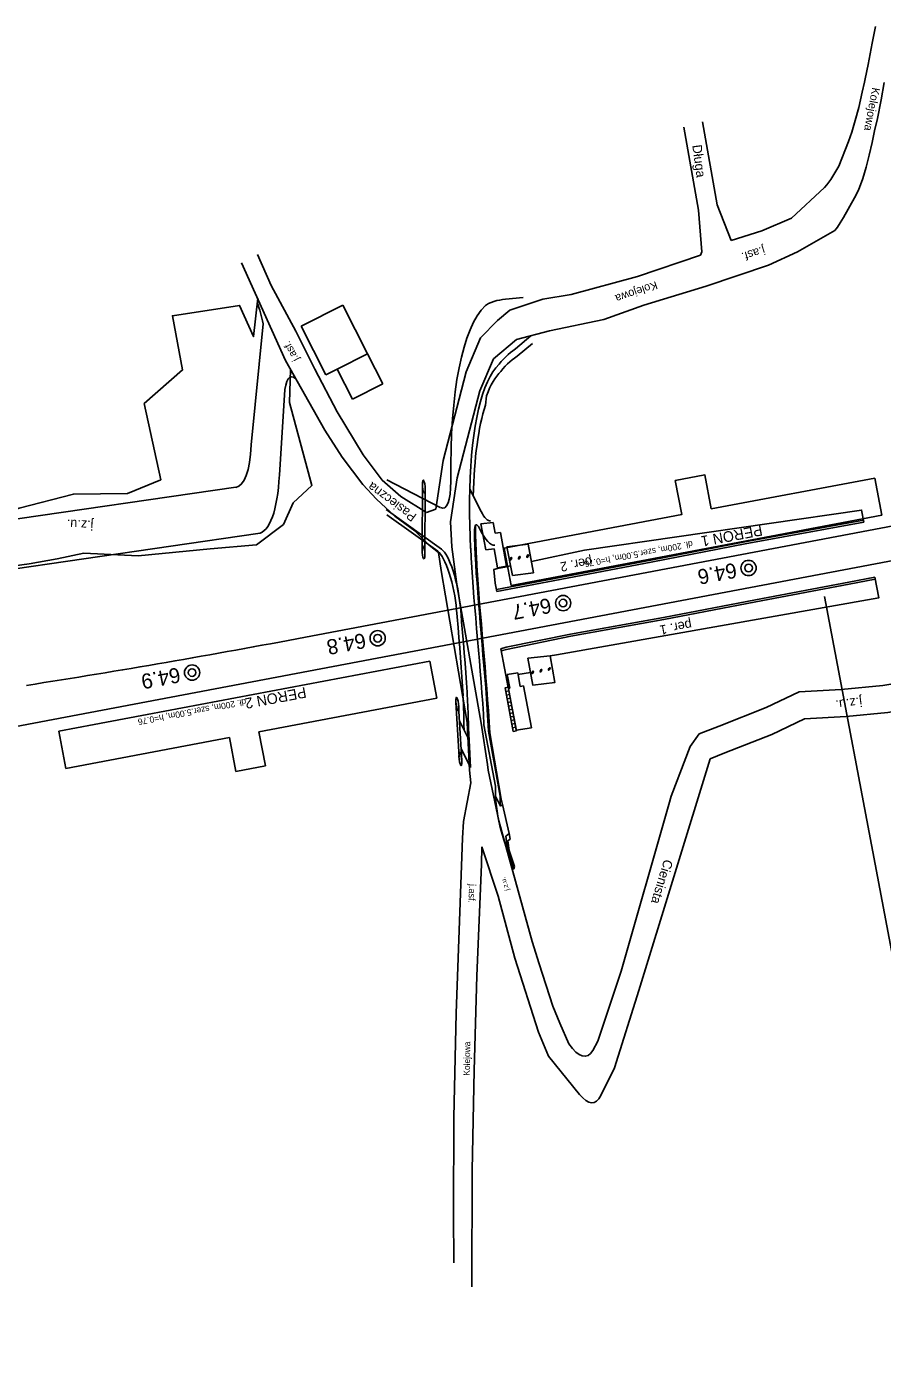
# Model space of a CAD drawing. Extents: x 6541740 to 6556805, y 5525233 to 5530361.
# Drawn here: x 6556344.1 to 6556457.6, y 5525917.2 to 5526092.1 of the extents above; entities that cross this region are included whole.
import ezdxf

# ---------------------------------------------------------------- set-up
doc = ezdxf.new("R2010")
doc.units = 0
for name, color, linetype in [('Default', 7, 'Continuous'), ('TOR_SCH-budynki', 7, 'Continuous'), ('TOR_SCH-hektometry', 7, 'Continuous'), ('TOR_SCH-obiekty istniejace', 7, 'Continuous'), ('TOR_SCH-obiekty projektowane', 7, 'Continuous'), ('TOR_SCH-opisy glowne', 7, 'Continuous'), ('TOR_SCH-perony', 7, 'Continuous'), ('TOR_SCH-przejazdy+drogi istniejace', 7, 'Continuous'), ('TOR_SCH-przejazdy+drogi projektowane', 7, 'Continuous'), ('TOR_SCH-tory projektowane', 7, 'Continuous')]:
    doc.layers.add(name, color=color, linetype=linetype)

# ---------------------------------------------------------------- blocks, each defined once
blk = doc.blocks.new('4010_1')
at = {"layer": 'Default'}
for radius in [0.75, 0.375]:
    blk.add_circle((0, 0), radius, dxfattribs=at)
blk = doc.blocks.new('311_2')
at = {"layer": 'Default'}
blk.add_circle((0, 0), 0.25, dxfattribs=at)

msp = doc.modelspace()

# ---------------------------------------------------------------- linework, layer by layer
at = {"layer": 'TOR_SCH-budynki'}
for p, q in [((6556380.55, 5526052.44), (6556386.06, 5526055.23)), ((6556386.06, 5526055.23), (6556389.33, 5526048.76)), ((6556383.82, 5526045.97), (6556380.55, 5526052.44)), ((6556389.33, 5526048.76), (6556385.3, 5526046.71)), ((6556389.33, 5526048.76), (6556391.35, 5526044.8)), ((6556385.3, 5526046.71), (6556383.82, 5526045.97)), ((6556387.33, 5526042.77), (6556385.3, 5526046.71)), ((6556391.35, 5526044.8), (6556387.33, 5526042.77)), ((6556404.35, 5526026.23), (6556405.97, 5526026.43)), ((6556404.98, 5526022.81), (6556404.35, 5526026.23)), ((6556406.23, 5526025), (6556405.97, 5526026.43)), ((6556406.23, 5526025), (6556406.92, 5526025.09)), ((6556407.74, 5526020.65), (6556406.92, 5526025.09)), ((6556404.98, 5526022.81), (6556406.09, 5526022.94)), ((6556406.56, 5526020.41), (6556406.09, 5526022.94)), ((6556406.56, 5526020.41), (6556407.74, 5526020.65)), ((6556407.83, 5526006.29), (6556409.22, 5526006.51)), ((6556408.17, 5526004.46), (6556407.83, 5526006.29)), ((6556409.56, 5526004.68), (6556409.22, 5526006.51)), ((6556407.95, 5526004.58), (6556407.54, 5526004.5)), ((6556407.98, 5526004.43), (6556408.17, 5526004.46)), ((6556409.03, 5525998.89), (6556407.98, 5526004.43)), ((6556409.56, 5526004.68), (6556410.01, 5526004.76)), ((6556411.04, 5525999.23), (6556410.01, 5526004.76)), ((6556409.03, 5525998.89), (6556411.04, 5525999.23))]:
    msp.add_line(p, q, dxfattribs=at)
msp.add_lwpolyline([(6556409.04, 5525998.82), (6556408.64, 5525998.74), (6556407.54, 5526004.5), (6556407.95, 5526004.58)], close=True, dxfattribs=at)
at = {"layer": 'TOR_SCH-obiekty istniejace'}
for p, q in [((6556455.03, 5526026.74), (6556439.3, 5526023.84)), ((6556455.08, 5526026.47), (6556439.35, 5526023.58)), ((6556407.68, 5526009.88), (6556406.97, 5526009.69)), ((6556406.97, 5526009.7), (6556407.95, 5526004.57)), ((6556407.73, 5526009.61), (6556407.02, 5526009.42)), ((6556407.64, 5526004.02), (6556408.04, 5526004.1)), ((6556407.73, 5526003.54), (6556408.13, 5526003.61)), ((6556407.82, 5526003.06), (6556408.22, 5526003.13)), ((6556407.91, 5526002.58), (6556408.31, 5526002.65)), ((6556408, 5526002.1), (6556408.41, 5526002.17)), ((6556408.09, 5526001.61), (6556408.5, 5526001.69)), ((6556408.18, 5526001.13), (6556408.59, 5526001.21)), ((6556408.27, 5526000.65), (6556408.68, 5526000.73)), ((6556408.36, 5526000.17), (6556408.77, 5526000.25)), ((6556408.46, 5525999.69), (6556408.86, 5525999.77)), ((6556408.55, 5525999.21), (6556408.95, 5525999.29)), ((6556409.04, 5525998.82), (6556408.64, 5525998.74))]:
    msp.add_line(p, q, dxfattribs=at)
for points in [[(6556455.08, 5526026.47), (6556454.77, 5526028.06), (6556418.06, 5526022.75), (6556411.03, 5526021.25)], [(6556439.3, 5526023.84), (6556427.06, 5526021.46), (6556414.8, 5526019.14), (6556406.41, 5526017.56)], [(6556439.35, 5526023.57), (6556427.12, 5526021.19), (6556414.85, 5526018.87), (6556406.46, 5526017.29)], [(6556408.28, 5526020.66), (6556407.73, 5526020.54), (6556406.55, 5526020.32), (6556406.06, 5526020.21), (6556406.25, 5526018.39), (6556406.46, 5526017.29)], [(6556456.51, 5526019.19), (6556453.07, 5526018.53), (6556440.73, 5526016.19), (6556428.54, 5526013.84), (6556416.23, 5526011.62), (6556407.68, 5526009.88)], [(6556456.56, 5526018.92), (6556453.12, 5526018.26), (6556440.78, 5526015.92), (6556428.59, 5526013.57), (6556416.28, 5526011.35), (6556407.73, 5526009.61)], [(6556456.51, 5526019.19), (6556457.05, 5526016.42), (6556414.35, 5526008.87), (6556413.51, 5526008.75)], [(6556410.92, 5526006.56), (6556409.26, 5526006.27)]]:
    msp.add_lwpolyline(points, dxfattribs=at)
for points in [[(6556408.53, 5526019.4), (6556411.31, 5526019.76), (6556410.6, 5526023.56), (6556407.79, 5526023.19)], [(6556410.57, 5526008.46), (6556413.51, 5526008.75), (6556414.14, 5526005.23), (6556411.23, 5526004.86)]]:
    msp.add_lwpolyline(points, close=True, dxfattribs=at)
at = {"layer": 'TOR_SCH-obiekty projektowane'}
for p, q in [((6556396.55, 5526022.78), (6556396.59, 5526031.52)), ((6556396.92, 5526022.1), (6556396.96, 5526030.84)), ((6556401.45, 5525995.33), (6556401.03, 5526002.62)), ((6556401.82, 5525994.84), (6556401.4, 5526002.12))]:
    msp.add_line(p, q, dxfattribs=at)
for centre, major_axis, ratio in [((6556396.78, 5526031.18), (0.074, -0.847), 0.2003), ((6556396.74, 5526022.44), (0.074, -0.847), 0.2003), ((6556401.22, 5526002.37), (0.101, -0.896), 0.178041), ((6556401.63, 5525995.08), (0.101, -0.896), 0.178041)]:
    msp.add_ellipse(centre, major_axis=major_axis, ratio=ratio, dxfattribs=at)
at = {"layer": 'TOR_SCH-opisy glowne'}
msp.add_lwpolyline([(6556465.13, 5525935.87), (6556449.87, 5526016.63), (6556449.87, 5526016.63), (6556449.87, 5526016.63)], dxfattribs=at)
at = {"layer": 'TOR_SCH-perony'}
for p, q in [((6556456.53, 5526032.31), (6556434.87, 5526028.21)), ((6556456.53, 5526032.31), (6556457.46, 5526027.4)), ((6556457.46, 5526027.4), (6556408.34, 5526018.09)), ((6556407.41, 5526023), (6556408.34, 5526018.09)), ((6556397.58, 5526008.06), (6556348.45, 5525998.75)), ((6556397.58, 5526008.06), (6556398.51, 5526003.15)), ((6556348.45, 5525998.75), (6556349.38, 5525993.84)), ((6556371.04, 5525997.94), (6556349.38, 5525993.84)), ((6556371.9, 5525993.42), (6556371.04, 5525997.94)), ((6556375.81, 5525994.16), (6556371.9, 5525993.42))]:
    msp.add_line(p, q, dxfattribs=at)
for points in [[(6556434.87, 5526028.21), (6556434.01, 5526032.73), (6556430.1, 5526031.99)], [(6556430.1, 5526031.99), (6556430.96, 5526027.47), (6556407.41, 5526023)], [(6556398.51, 5526003.15), (6556374.95, 5525998.68), (6556375.81, 5525994.16)]]:
    msp.add_lwpolyline(points, dxfattribs=at)
at = {"layer": 'TOR_SCH-przejazdy+drogi istniejace'}
for p, q in [((6556456.62, 5526092.14), (6556456.19, 5526089.94)), ((6556456.19, 5526089.94), (6556455.65, 5526087.08)), ((6556455.65, 5526087.08), (6556455.25, 5526085.22)), ((6556455.25, 5526085.22), (6556455.14, 5526084.75)), ((6556454.83, 5526083.41), (6556454.39, 5526081.4)), ((6556455.14, 5526084.75), (6556454.83, 5526083.41)), ((6556457.36, 5526082.42), (6556457.77, 5526084.72)), ((6556454.39, 5526081.4), (6556453.93, 5526079.68)), ((6556456.87, 5526079.96), (6556457.36, 5526082.42)), ((6556453.93, 5526079.68), (6556453.48, 5526078.12)), ((6556456.5, 5526078.29), (6556456.87, 5526079.96)), ((6556433.19, 5526067.78), (6556431.21, 5526078.78)), ((6556433.7, 5526079.51), (6556435.66, 5526068.52)), ((6556453.48, 5526078.12), (6556453.06, 5526076.91)), ((6556456.16, 5526076.78), (6556456.5, 5526078.29)), ((6556453.06, 5526076.91), (6556451.76, 5526073.62)), ((6556455.77, 5526075.1), (6556456.16, 5526076.78)), ((6556455.38, 5526073.5), (6556455.77, 5526075.1)), ((6556451.25, 5526072.73), (6556450.7, 5526071.88)), ((6556451.76, 5526073.62), (6556451.25, 5526072.73)), ((6556454.96, 5526072), (6556455.38, 5526073.5)), ((6556450.15, 5526071.17), (6556449.86, 5526070.82)), ((6556450.7, 5526071.88), (6556450.15, 5526071.17)), ((6556454.37, 5526070.45), (6556454.96, 5526072)), ((6556445.48, 5526066.74), (6556449.86, 5526070.82)), ((6556452.39, 5526066.81), (6556453.85, 5526069.43)), ((6556453.85, 5526069.43), (6556454.37, 5526070.45)), ((6556433.59, 5526062.26), (6556433.19, 5526067.78)), ((6556435.66, 5526068.52), (6556437.49, 5526063.78)), ((6556441.56, 5526065.05), (6556445.48, 5526066.74)), ((6556451.6, 5526065.54), (6556451.94, 5526066.1)), ((6556451.94, 5526066.1), (6556452.39, 5526066.81)), ((6556441.56, 5526065.05), (6556437.49, 5526063.78)), ((6556451.22, 5526065.09), (6556446.28, 5526062.28)), ((6556451.22, 5526065.09), (6556451.6, 5526065.54)), ((6556433.59, 5526062.26), (6556433.42, 5526061.83)), ((6556446.28, 5526062.28), (6556442.45, 5526060.53)), ((6556378.44, 5526047.89), (6556372.63, 5526060.82)), ((6556374.74, 5526061.92), (6556376.58, 5526057.81)), ((6556442.45, 5526060.53), (6556434.17, 5526057.72)), ((6556376.58, 5526057.81), (6556379.83, 5526051.77)), ((6556379.83, 5526051.77), (6556382.34, 5526046.71)), ((6556383.68, 5526038.66), (6556378.44, 5526047.89)), ((6556382.34, 5526046.71), (6556385.29, 5526041.08)), ((6556385.29, 5526041.08), (6556388.76, 5526035.37)), ((6556385.97, 5526035.06), (6556383.68, 5526038.66)), ((6556388.71, 5526031.46), (6556385.97, 5526035.06)), ((6556388.76, 5526035.37), (6556391.27, 5526032.01)), ((6556357.54, 5526030.26), (6556361.94, 5526032.06)), ((6556390.52, 5526029.51), (6556388.71, 5526031.46)), ((6556391.27, 5526032.01), (6556393.73, 5526029.86)), ((6556392.95, 5526027.24), (6556390.52, 5526029.51)), ((6556393.73, 5526029.86), (6556397.14, 5526027.75)), ((6556395.59, 5526025.33), (6556392.95, 5526027.24)), ((6556397.14, 5526027.75), (6556398.36, 5526028.18)), ((6556397.49, 5526023.42), (6556395.59, 5526025.33)), ((6556398.72, 5526022.45), (6556397.49, 5526023.42)), ((6556434.7, 5525995.11), (6556425.26, 5525964.4)), ((6556403.02, 5525991.93), (6556402.85, 5525993.6)), ((6556405.33, 5525993.59), (6556406.72, 5525986.89)), ((6556402.05, 5525986.82), (6556403.02, 5525991.93)), ((6556422.91, 5525966.97), (6556429.23, 5525989.04)), ((6556401.91, 5525984.59), (6556402.05, 5525986.82)), ((6556406.72, 5525986.89), (6556411.15, 5525970.92)), ((6556401.08, 5525961.39), (6556401.91, 5525984.59)), ((6556404.49, 5525983.43), (6556404.42, 5525981.12)), ((6556406.64, 5525976.92), (6556404.49, 5525983.43)), ((6556404.42, 5525981.12), (6556403.82, 5525966.35)), ((6556408.86, 5525968.68), (6556406.64, 5525976.92)), ((6556408.86, 5525968.68), (6556411.99, 5525958.89)), ((6556403.82, 5525966.35), (6556403.44, 5525953.83)), ((6556419.85, 5525957.71), (6556422.91, 5525966.97)), ((6556425.26, 5525964.4), (6556422.03, 5525954.15)), ((6556400.76, 5525947.58), (6556401.08, 5525961.39)), ((6556419.19, 5525956.48), (6556419.85, 5525957.71)), ((6556403.44, 5525953.83), (6556403.21, 5525940.6)), ((6556422.03, 5525954.15), (6556420.24, 5525950.51)), ((6556400.72, 5525934.88), (6556400.76, 5525947.58)), ((6556403.21, 5525940.6), (6556403.16, 5525925.15)), ((6556400.78, 5525928.33), (6556400.72, 5525934.88))]:
    msp.add_line(p, q, dxfattribs=at)
for points in [[(6556406.55, 5526053.17), (6556408.16, 5526054.56), (6556412.53, 5526056.01), (6556416.29, 5526056.63), (6556425.11, 5526058.99), (6556433.42, 5526061.83)], [(6556406.03, 5526048.1), (6556409.06, 5526050.66), (6556413.45, 5526051.8), (6556420.65, 5526053.29), (6556425.91, 5526055.22), (6556434.17, 5526057.72)], [(6556361.94, 5526032.06), (6556359.76, 5526042.18), (6556364.83, 5526046.64), (6556363.49, 5526053.81), (6556372.39, 5526055.17), (6556374.24, 5526051.04), (6556374.79, 5526056.16)], [(6556398.36, 5526028.18), (6556399.33, 5526034.63), (6556402.41, 5526046.4), (6556404.31, 5526050.87), (6556406.55, 5526053.17)], [(6556358.96, 5526022.02), (6556368.49, 5526022.94), (6556374.61, 5526023.44), (6556378.19, 5526026.14), (6556379.47, 5526029), (6556381.95, 5526031.33), (6556378.97, 5526042.31), (6556379.13, 5526046.68), (6556379.13, 5526046.68), (6556379.13, 5526046.68)], [(6556405.33, 5525993.59), (6556405.23, 5525994.36), (6556404.4, 5525999.82), (6556401.21, 5526017.88), (6556400.48, 5526023.18), (6556400.33, 5526026.51), (6556401.21, 5526032.34), (6556404.22, 5526043.86), (6556406.03, 5526048.11)], [(6556301.03, 5526021), (6556308.94, 5526022.23), (6556312.43, 5526023.7), (6556323.46, 5526023.91), (6556326.25, 5526024.08), (6556330.73, 5526025.47), (6556332.55, 5526025.73), (6556335.44, 5526025.81), (6556343.2, 5526028.3), (6556350.37, 5526030.18), (6556357.54, 5526030.26)], [(6556302.27, 5526014.25), (6556310.2, 5526015.68), (6556313.66, 5526016.39), (6556324.34, 5526017.68), (6556327.42, 5526017.52), (6556333.76, 5526019.49), (6556344.51, 5526020.95), (6556348.22, 5526021.61), (6556351.75, 5526022.37), (6556358.96, 5526022.02)], [(6556402.85, 5525993.6), (6556402.51, 5525999.9), (6556399.1, 5526020.04), (6556398.72, 5526022.45)], [(6556429.23, 5525989.04), (6556429.57, 5525990.16), (6556432.08, 5525996.72), (6556433.28, 5525998.41), (6556435.93, 5525999.45), (6556442.15, 5526001.91), (6556446.51, 5526003.97), (6556452.05, 5526004.3), (6556457.57, 5526004.84), (6556464.32, 5526005.92), (6556470.57, 5526007.08)], [(6556434.7, 5525995.11), (6556436.65, 5525995.88), (6556442.87, 5525998.34), (6556447.21, 5526000.39), (6556452.71, 5526000.72), (6556458.23, 5526001.25), (6556464.99, 5526002.34), (6556471.29, 5526003.55)], [(6556414.79, 5525960.08), (6556413.88, 5525962.34), (6556412.06, 5525967.94), (6556411.15, 5525970.92)], [(6556414.79, 5525960.08), (6556416.01, 5525957.36), (6556416.01, 5525957.36)], [(6556411.99, 5525958.89), (6556413.32, 5525955.69), (6556417.42, 5525950.64)]]:
    msp.add_lwpolyline(points, dxfattribs=at)
for centre, major_axis, start_param, end_param in [((6556415.36, 5525971.09), (-2.91, 15.37), 2.627221, 3.412235), ((6556416.45, 5525964.24), (-2.78, 14.68), 2.705396, 3.458735)]:
    msp.add_ellipse(centre, major_axis=major_axis, ratio=0.25, start_param=start_param, end_param=end_param, dxfattribs=at)
at = {"layer": 'TOR_SCH-przejazdy+drogi projektowane'}
for p, q in [((6556375.52, 5526052.74), (6556373.92, 5526036.69)), ((6556378.32, 5526043.3), (6556377.65, 5526032.72)), ((6556404.94, 5526041.97), (6556405.08, 5526043.2)), ((6556371.87, 5526031.08), (6556303.1, 5526021.15)), ((6556391.89, 5526032.07), (6556398.97, 5526028.39)), ((6556404.38, 5526027.86), (6556402.87, 5526030.82)), ((6556391.78, 5526028.16), (6556399.14, 5526022.89)), ((6556391.87, 5526027.43), (6556398.62, 5526022.6)), ((6556374.8, 5526024.94), (6556304.29, 5526014.76)), ((6556401.12, 5526014.86), (6556401.2, 5526013.9)), ((6556401.71, 5526014.23), (6556401.67, 5526014.72)), ((6556401.71, 5526014.23), (6556401.79, 5526013.24)), ((6556403.78, 5526012.39), (6556403.82, 5526011.9)), ((6556403.82, 5526011.9), (6556403.91, 5526010.92)), ((6556404.38, 5526011.74), (6556404.42, 5526011.25)), ((6556404.52, 5526011.58), (6556404.65, 5526010.1)), ((6556404.42, 5526011.25), (6556404.5, 5526010.26)), ((6556401.51, 5526000.14), (6556402.8, 5525997.56)), ((6556404.75, 5525999.6), (6556406.29, 5525991.49)), ((6556402.8, 5525997.56), (6556402.97, 5525993.97)), ((6556405.36, 5525998.78), (6556406.9, 5525990.17)), ((6556405.51, 5525998.56), (6556407.05, 5525989.77)), ((6556401.72, 5525996.46), (6556402.97, 5525993.97)), ((6556406.93, 5525988.84), (6556406.29, 5525990.17)), ((6556406.93, 5525988.84), (6556407.21, 5525989.07)), ((6556407.21, 5525989.07), (6556407.05, 5525989.77)), ((6556407.21, 5525989.07), (6556408.09, 5525985.21)), ((6556407.66, 5525984.86), (6556408.08, 5525985.2)), ((6556408.09, 5525985.21), (6556408.24, 5525984.48)), ((6556407.39, 5525984.39), (6556408.72, 5525980.45)), ((6556407.66, 5525984.86), (6556407.92, 5525982.83)), ((6556407.93, 5525984.23), (6556408.24, 5525984.48)), ((6556407.93, 5525984.23), (6556408.09, 5525982.97)), ((6556408.09, 5525982.97), (6556408.81, 5525980.85)), ((6556408.81, 5525980.85), (6556408.7, 5525980.53))]:
    msp.add_line(p, q, dxfattribs=at)
for points in [[(6556409.95, 5526056.22), (6556407.6, 5526055.99), (6556407.22, 5526055.95), (6556406.84, 5526055.89), (6556406.46, 5526055.81), (6556406.08, 5526055.71), (6556405.71, 5526055.57), (6556405.34, 5526055.41), (6556404.94, 5526055.18)], [(6556410.98, 5526051.13), (6556408.91, 5526049.43), (6556408.58, 5526049.18), (6556408.26, 5526048.93), (6556407.94, 5526048.66), (6556407.63, 5526048.38), (6556407.32, 5526048.07), (6556407.03, 5526047.73), (6556406.75, 5526047.38)], [(6556411.18, 5526050.15), (6556409.13, 5526048.46), (6556408.8, 5526048.21), (6556408.47, 5526047.96), (6556408.16, 5526047.7), (6556407.85, 5526047.42), (6556407.55, 5526047.11), (6556407.26, 5526046.77), (6556406.98, 5526046.43)], [(6556402.99, 5526023.01), (6556403.06, 5526021.72), (6556403.14, 5526020.45), (6556403.23, 5526019.16), (6556403.33, 5526017.84), (6556403.43, 5526016.5), (6556403.55, 5526015.15), (6556403.66, 5526013.78), (6556403.78, 5526012.39)], [(6556403.6, 5526022.17), (6556403.67, 5526020.9), (6556403.74, 5526019.67), (6556403.83, 5526018.41), (6556403.93, 5526017.13), (6556404.03, 5526015.82), (6556404.14, 5526014.48), (6556404.26, 5526013.12), (6556404.38, 5526011.74)], [(6556403.75, 5526021.95), (6556403.82, 5526020.69), (6556403.89, 5526019.48), (6556403.98, 5526018.23), (6556404.08, 5526016.95), (6556404.18, 5526015.64), (6556404.29, 5526014.31), (6556404.41, 5526012.95), (6556404.52, 5526011.58)], [(6556401.63, 5526015.15), (6556401.67, 5526014.72)], [(6556401.2, 5526013.9), (6556401.32, 5526012.52), (6556401.43, 5526011.16), (6556401.54, 5526009.82), (6556401.65, 5526008.51), (6556401.74, 5526007.22), (6556401.83, 5526005.97), (6556401.91, 5526004.74), (6556401.98, 5526003.47)], [(6556401.79, 5526013.25), (6556401.91, 5526011.86), (6556402.03, 5526010.49), (6556402.14, 5526009.14), (6556402.25, 5526007.8), (6556402.35, 5526006.48), (6556402.44, 5526005.19), (6556402.52, 5526003.92), (6556402.59, 5526002.63)], [(6556403.91, 5526010.92), (6556404.03, 5526009.52), (6556404.15, 5526008.11), (6556404.26, 5526006.7), (6556404.38, 5526005.28), (6556404.48, 5526003.85), (6556404.58, 5526002.42), (6556404.67, 5526001), (6556404.75, 5525999.6)], [(6556404.5, 5526010.26), (6556404.62, 5526008.86), (6556404.74, 5526007.45), (6556404.86, 5526006.01), (6556404.98, 5526004.57), (6556405.09, 5526003.11), (6556405.19, 5526001.64), (6556405.28, 5526000.17), (6556405.36, 5525998.78)], [(6556404.65, 5526010.1), (6556404.77, 5526008.7), (6556404.89, 5526007.28), (6556405.01, 5526005.84), (6556405.13, 5526004.39), (6556405.24, 5526002.92), (6556405.34, 5526001.45), (6556405.43, 5525999.97), (6556405.51, 5525998.56)], [(6556402.71, 5525999.11), (6556402.8, 5525997.56)]]:
    msp.add_lwpolyline(points, dxfattribs=at)
for centre, major_axis, start_param, end_param in [((6556373.92, 5526051.52), (-1.35, 7.12), 4.836985, 5.265781), ((6556417.16, 5526002.73), (-10.16, 53.6), 0.164948, 0.948683), ((6556417.16, 5526002.73), (-8.65, 45.64), 0.165669, 0.861162), ((6556417.16, 5526002.73), (-8.46, 44.65), 0.165204, 0.391379), ((6556380.54, 5526038.6), (-1.35, 7.12), 5.955892, 7.087106), ((6556417.16, 5526002.73), (-8.37, 44.16), 0.431421, 0.861162), ((6556368.79, 5526047.54), (-3.12, 16.46), 3.1306, 3.945513), ((6556370.53, 5526047.8), (-4.33, 22.84), 3.1306, 3.945513), ((6556397.89, 5526036.17), (-1.49, 7.86), 2.947411, 4.090276), ((6556417.16, 5526002.73), (-8.65, 45.64), 0.861162, 1.064524), ((6556404.49, 5526032.52), (-1.12, 5.9), 2.431958, 3.141593), ((6556404.11, 5526024.14), (-0.37, 1.97), 5.522961, 7.268235), ((6556417.16, 5526002.73), (-8.19, 43.18), 0.954421, 1.064524), ((6556404.49, 5526032.52), (-1.72, 9.1), 2.381369, 3.141593), ((6556417.16, 5526002.73), (-8.28, 43.67), 0.985049, 1.064524), ((6556399.33, 5526016.82), (-1.12, 5.9), 4.326117, 6.026682), ((6556399.84, 5526017.11), (-1.12, 5.9), 4.325492, 6.026682), ((6556388.41, 5526022.91), (-8.28, 43.67), 4.08494, 4.206117), ((6556388.41, 5526022.91), (-8.65, 45.64), 4.117029, 4.206117), ((6556408.12, 5525987.53), (-1.12, 5.9), 0.787457, 1.1939), ((6556408.12, 5525987.53), (-1.12, 5.9), 1.194409, 2.083908), ((6556408.12, 5525987.53), (-0.74, 3.93), 0.787457, 1.181178)]:
    msp.add_ellipse(centre, major_axis=major_axis, ratio=0.25, start_param=start_param, end_param=end_param, dxfattribs=at)
at = {"layer": 'TOR_SCH-tory projektowane'}
for p, q in [((6556735.03, 5526073.73), (6555909.41, 5525917.23)), ((6556465.14, 5526027.15), (6556381.1, 5526011.22))]:
    msp.add_line(p, q, dxfattribs=at)
msp.add_ellipse((6552935.72, 5544187.56), major_axis=(-3445.38, 18176.34), ratio=0.25, start_param=3.133485, end_param=3.141593, dxfattribs=at)

# ---------------------------------------------------------------- block references
at = {"layer": 'TOR_SCH-hektometry', "xscale": 1.345963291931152, "yscale": 1.345963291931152}
for p in [(6556439.8, 5526020.39), (6556415.24, 5526015.74), (6556390.67, 5526011.08), (6556366.09, 5526006.53)]:
    msp.add_blockref('4010_1', p, dxfattribs=at)
at = {"layer": 'TOR_SCH-obiekty istniejace', "xscale": 0.30824718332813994, "yscale": 0.8110374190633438, "rotation": -26.43658286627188}
for p in [(6556409.43, 5526021.76), (6556410.54, 5526021.97), (6556408.33, 5526021.61), (6556411.2, 5526006.58), (6556412.31, 5526006.77), (6556413.4, 5526007.03)]:
    msp.add_blockref('311_2', p, dxfattribs=at)

# ---------------------------------------------------------------- texts
at = {"layer": 'TOR_SCH-hektometry'}
for s, p in [('64.6', (6556438.03, 5526021.1)), ('64.7', (6556413.46, 5526016.44)), ('64.8', (6556388.9, 5526011.79)), ('64.9', (6556364.32, 5526007.24))]:
    msp.add_text(s, height=2, rotation=190.7691, dxfattribs=at).set_placement(p)
at = {"layer": 'TOR_SCH-perony'}
for s, height, rotation, p in [('PERON 1', 1.4, 190.7127, (6556441.49, 5526026.1)), ('dł. 200m, szer.5.00m, h=0.76', 0.84, 190.7075, (6556432.33, 5526024.01)), ('per. 2', 1.251, 190.4077, (6556418.97, 5526021.88)), ('per. 1', 1.251, 190.4077, (6556432.16, 5526013.51)), ('PERON 2', 1.4, 190.7127, (6556381.07, 5526004.62)), ('dł. 200m, szer.5.00m, h=0.76', 0.84, 190.7075, (6556373.17, 5526003.09))]:
    msp.add_text(s, height=height, rotation=rotation, dxfattribs=at).set_placement(p)
at = {"layer": 'TOR_SCH-przejazdy+drogi istniejace'}
for s, height, rotation, p in [('Kolejowa', 1.068, 259.262, (6556456.18, 5526084.11)), ('Długa', 1.25, 277.69, (6556432.34, 5526076.39)), ('j.asf.', 1.123, 197.5481, (6556441.78, 5526063.05)), ('Kolejowa', 1.068, 198.8857, (6556427.52, 5526058.4)), ('j.asf.', 1.001, 118.3326, (6556380.29, 5526048.07)), ('Pasieczna', 1.21, 143.569, (6556395.92, 5526027.41)), ('j.z.u.', 1.248, 177.2502, (6556353.03, 5526026.65)), ('j.z.u.', 1.248, 187.5853, (6556454.76, 5526003.3)), ('Cienista', 1.247, 252.9137, (6556428.63, 5525981.87)), ('j.asf.', 0.895, 267.214, (6556402.8, 5525978.54)), ('j.z.u.', 0.633, 108.0122, (6556408.1, 5525977.73)), ('Kolejowa', 0.832, 89.0496, (6556402.87, 5525953.12))]:
    msp.add_text(s, height=height, rotation=rotation, dxfattribs=at).set_placement(p)

doc.saveas('drawing.dxf')
